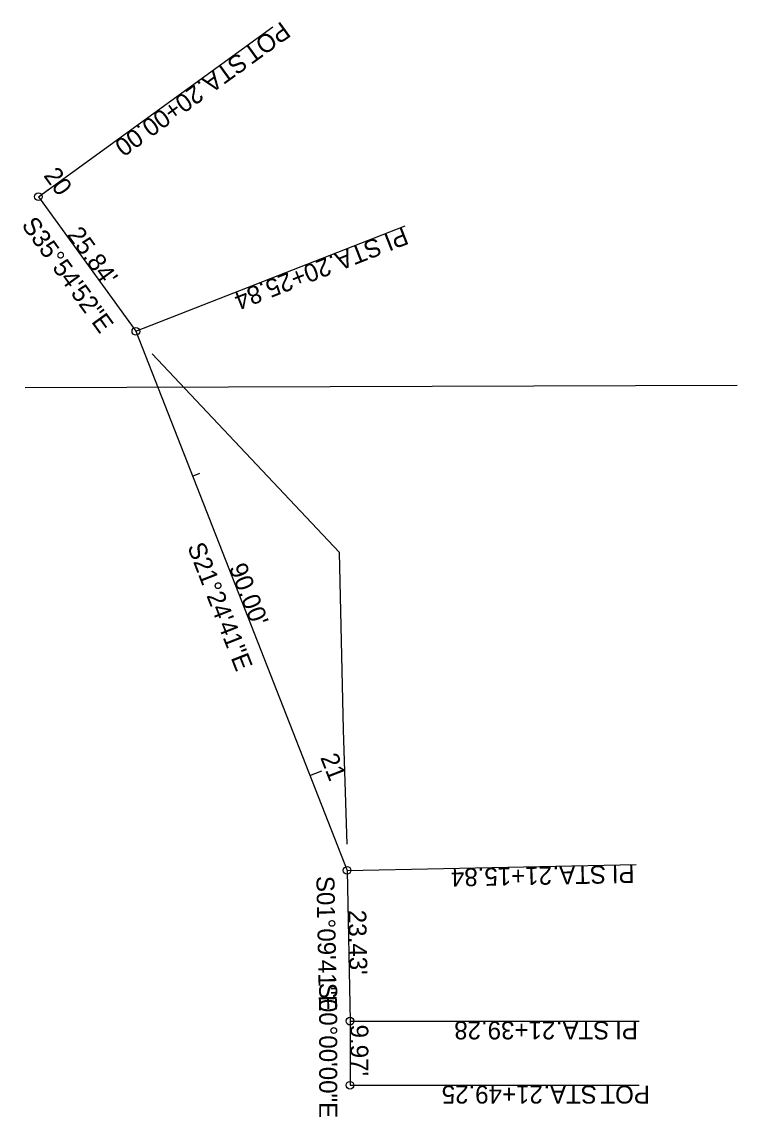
# Model space of a CAD drawing. Extents: x 2320764 to 2320876, y 575339 to 575509.
import ezdxf

# ---------------------------------------------------------------- set-up
doc = ezdxf.new("R2010")
doc.units = 0
for name, color, linetype in [('GE_P_Alignment', 7, 'Continuous'), ('GE_P_Alignment_100_Bearings', 7, 'Continuous'), ('GE_P_Alignment_100_Cardinal_Points', 7, 'Continuous'), ('GE_P_Alignment_100_Distances', 7, 'Continuous'), ('GE_P_Alignment_100_Stations', 7, 'Continuous'), ('SC_Scratch1', 7, 'Continuous')]:
    doc.layers.add(name, color=color, linetype=linetype)

msp = doc.modelspace()

# ---------------------------------------------------------------- linework, layer by layer
at = {"layer": 'GE_P_Alignment'}
for p, q in [((2320766.99, 575481.72), (2320782.15, 575460.79)), ((2320782.15, 575460.79), (2320815, 575377)), ((2320815, 575377), (2320815.48, 575353.57)), ((2320815.46, 575353.57), (2320815.46, 575343.6))]:
    msp.add_line(p, q, dxfattribs=at)
at = {"layer": 'GE_P_Alignment_100_Cardinal_Points'}
for p, q in [((2320766.99, 575481.72), (2320803.43, 575508.11)), ((2320782.15, 575460.79), (2320824.04, 575477.21)), ((2320815, 575377), (2320859.99, 575377.91)), ((2320815.46, 575353.57), (2320860.46, 575353.57)), ((2320815.46, 575343.6), (2320860.46, 575343.6))]:
    msp.add_line(p, q, dxfattribs=at)
for centre in [(2320766.99, 575481.72), (2320782.15, 575460.79), (2320815, 575377), (2320815.46, 575353.57), (2320815.46, 575343.6)]:
    msp.add_circle(centre, 0.6, dxfattribs=at)
at = {"layer": 'GE_P_Alignment_100_Stations'}
for p, q in [((2320766.99, 575481.72), (2320768.61, 575482.89)), ((2320790.96, 575438.3), (2320792.08, 575438.73)), ((2320809.22, 575391.75), (2320811.08, 575392.48))]:
    msp.add_line(p, q, dxfattribs=at)
at = {"layer": 'SC_Scratch1'}
for p, q in [((2320782.15, 575460.79), (2320815, 575377)), ((2320784.66, 575457.31), (2320813.75, 575426.44)), ((2320764.94, 575452.04), (2320875.67, 575452.41)), ((2320813.75, 575426.44), (2320814.41, 575398.85)), ((2320814.41, 575398.85), (2320814.94, 575381.1))]:
    msp.add_line(p, q, dxfattribs=at)

# ---------------------------------------------------------------- texts
at = {"layer": 'GE_P_Alignment_100_Bearings'}
for s, rotation, p in [('S35°54\'52"E', 305.9145, (2320764.26, 575477.29)), ('S21°24\'41"E', 291.4114, (2320790.11, 575427.32)), ('S01°09\'41"E', 271.1613, (2320810.22, 575376.12)), ('S00°00\'00"E', 270, (2320810.66, 575359.52))]:
    msp.add_text(s, height=2.8, rotation=rotation, dxfattribs=at).set_placement(p)
at = {"layer": 'GE_P_Alignment_100_Cardinal_Points'}
for s, rotation, p in [('POT', 215.9145, (2320804.82, 575509.06)), (' STA. ', 215.9145, (2320798.99, 575504.84)), ('20+00.00', 215.9145, (2320791.33, 575499.3)), ('PI', 201.4114, (2320823.78, 575477.07)), (' STA. ', 201.4114, (2320820.62, 575475.83)), ('20+25.84', 201.4114, (2320811.82, 575472.38)), ('21+15.84', 181.1613, (2320846.85, 575377.6)), (' STA. ', 181.1613, (2320856.3, 575377.79)), ('PI', 181.1613, (2320859.69, 575377.86)), ('21+39.28', 180, (2320847.39, 575353.53)), (' STA. ', 180, (2320856.84, 575353.53)), ('PI', 180, (2320860.23, 575353.53)), ('21+49.25', 180, (2320845.45, 575343.56)), (' STA. ', 180, (2320854.9, 575343.56)), ('POT', 180, (2320862.1, 575343.56))]:
    msp.add_text(s, height=2.8, rotation=rotation, dxfattribs=at).set_placement(p)
at = {"layer": 'GE_P_Alignment_100_Distances'}
for s, rotation, p in [("25.84'", 305.9145, (2320771.34, 575475.78)), ("90.00'", 291.4114, (2320796.58, 575424.09)), ("23.43'", 271.1613, (2320815.17, 575370.84)), ("9.97'", 270, (2320815.51, 575353.03))]:
    msp.add_text(s, height=2.8, rotation=rotation, dxfattribs=at).set_placement(p)
at = {"layer": 'GE_P_Alignment_100_Stations'}
for s, rotation, p in [('20', 305.9145, (2320767.7, 575484.99)), ('21', 291.4114, (2320810.8, 575394.55))]:
    msp.add_text(s, height=2.8, rotation=rotation, dxfattribs=at).set_placement(p)

doc.saveas('drawing.dxf')
